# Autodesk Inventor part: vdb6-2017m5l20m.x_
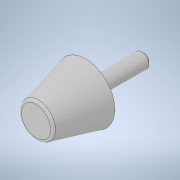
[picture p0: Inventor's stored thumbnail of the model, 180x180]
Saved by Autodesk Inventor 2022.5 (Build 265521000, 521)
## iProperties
Created: 2021-08
Part Number: vdb6-2017m5l20m.x_
Material: 一般
Document SubType Name: Modeling
Designer: ImaoCorp
Density: 1 g/cm^3
Appearance: 既定
Sending System: SOLIDWORKS 2019-2019304
MC: AMD64
MC_MODEL: Intel64 Family 6 Model 60 Stepping 3, GenuineIntel
OS: Windows_NT
FRU: Parasolid Version 31.0, build 290,  9- 1-2019
FORMAT: text
GUISE: transmit
KEY: vdb6-2017m5l20m
FILE: vdb6-2017m5l20m.x_t
DATE: Wed Aug 11 15:01:16 2021
Author: ImaoCorp
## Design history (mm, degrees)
feature "Base1"
node "ソリッド1"
